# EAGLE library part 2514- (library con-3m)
3M (TM) Pak 100 4-Wall Header Source: 3M
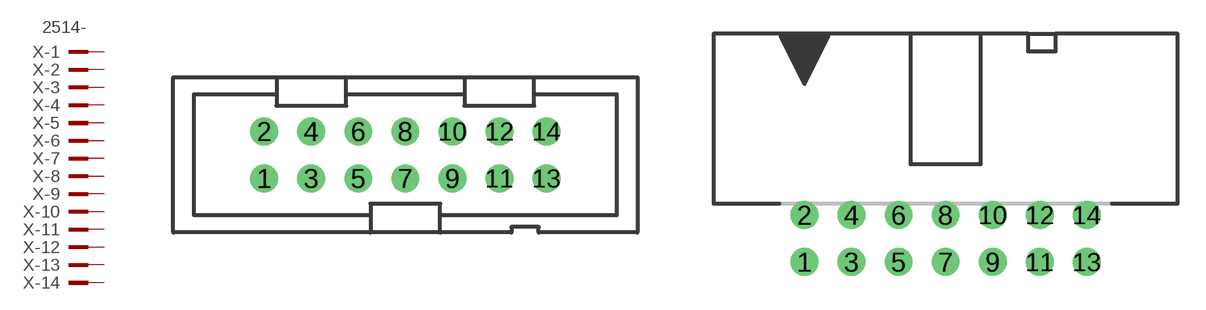
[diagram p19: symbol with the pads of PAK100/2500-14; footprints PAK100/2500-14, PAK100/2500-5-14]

Designator prefix X; gates -1=PINV -2=PIN -3=PIN -4=PIN -5=PIN -6=PIN -7=PIN -8=PIN -9=PIN -10=PIN -11=PIN -12=PIN -13=PIN -14=PIN

## 2514- (OC_FARNELL: unknown; OC_NEWARK: unknown)  [PAK100/2500-14]
1  -1:KL  pas
2  -2:KL  pas
3  -3:KL  pas
4  -4:KL  pas
5  -5:KL  pas
6  -6:KL  pas
7  -7:KL  pas
8  -8:KL  pas
9  -9:KL  pas
10  -10:KL  pas
11  -11:KL  pas
12  -12:KL  pas
13  -13:KL  pas
14  -14:KL  pas

## 2514-5 (MPN: N2514-5002RB; OC_FARNELL: 1788673; OC_NEWARK: 97K6709)  [PAK100/2500-5-14]
Pads as for PAK100/2500-14

## Footprint PAK100/2500-14 (pad centres in mm)
3M (TM) Pak 100 4-Wall Header Straight Source: 3M
drill 1 pad 1.422 round: 1 -7.62,-1.27; 2 -7.62,1.27; 3 -5.08,-1.27; 4 -5.08,1.27; 5 -2.54,-1.27; 6 -2.54,1.27; 7 0,-1.27; 8 0,1.27; 9 2.54,-1.27; 10 2.54,1.27; 11 5.08,-1.27; 12 5.08,1.27; 13 7.62,-1.27; 14 7.62,1.27

## Footprint PAK100/2500-5-14 (pad centres in mm)
3M (TM) Pak 100 4-Wall Header Right Angle Source: 3M
drill 1 pad 1.422 round: 1 -7.62,-1.27; 2 -7.62,1.27; 3 -5.08,-1.27; 4 -5.08,1.27; 5 -2.54,-1.27; 6 -2.54,1.27; 7 0,-1.27; 8 0,1.27; 9 2.54,-1.27; 10 2.54,1.27; 11 5.08,-1.27; 12 5.08,1.27; 13 7.62,-1.27; 14 7.62,1.27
